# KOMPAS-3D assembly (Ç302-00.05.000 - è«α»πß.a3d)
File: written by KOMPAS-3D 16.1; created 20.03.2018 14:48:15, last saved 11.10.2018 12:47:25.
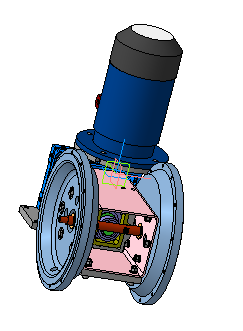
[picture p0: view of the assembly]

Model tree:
1. Массив по концентрической сетке:1  (2 pattern instances)
     Шаг 2 = 360
2. Массив по концентрической сетке:2  (4 pattern instances)
     Шаг 2 = 360
3. Сечение поверхностью:3
4. Сечение поверхностью:4
5. Сечение поверхностью:2  (labels: А302-00.05.000; C:\Program Files\ASCON\KOMPAS-3D V16\Sys\bo_atr.lat; SYSTEM_PROPERTY_ADDITIONAL_FOR:5.000000)
     Расстояние = -4; Расстояние = 4; Расстояние = 1

Referenced files in Z:\Мембранные насосы\Мембранный электропривод\А302-00.00.000 - ASTRA-302 (МЭ200)\3Д\: А302-00.20.000 - Мотор-редуктор.a3d, А302-00.05.002 - Ловитель.m3d, А302-00.05.001 - Основание.m3d
Referenced files in C:\Program Files\ASCON\KOMPAS-3D V16\Libs\PartLib\DATA\vault\Methods\Kompas\3D\: PLib_Washer_1_712.m3d
Referenced files in C:\Program Files\ASCON\KOMPAS-3D V16\Libs\PartLib\DATA\VAULT\Methods\kompas\3d\: PLib_Washer_2_712.m3d, PLib_Bolt_1_900.m3d, PLib_Nut_OST92_900.m3d
Referenced files in Z:\1 ПКИ 3D\1 Крепеж стандартный\Подшипник\: Подшипник радиально-упорный 80х40х18 7208 BEP SKF.m3d, Подшипниковый узел UCF207 ISB EcoLine.m3d
Referenced files in Z:\Мембранные насосы\Мембранный электропривод\А302-00.00.000 - ASTRA-302 (МЭ200)\3Д ПВХ\Отработка\: Фиксатор.m3d, Упор.m3d, Упор-1.m3d
Referenced files in Z:\Мембранные насосы\Мембранный электропривод\А302-00.00.000 - ASTRA-302 (МЭ200)\Чертежи\: А302-00.20.000  - Мотор-редуктор.spw
Referenced files: GRAPHIC.TDP
Referenced files in \\192.168.87.28\Konstructor_doc\Мембранные насосы\Мембранный электропривод\А302-00.00.000 - ASTRA-302 (МЭ200)\Чертежи\: А302-00.05.002 - Ловитель.cdw, А302-00.05.001 - Основание.cdw
Referenced files in Z:\Мембранные насосы\Мембранный электропривод\А302-00.00.000 - ASTRA-302 (МЭ200)\3Д ПВХ\: А302-01.05.012 - Фиксатор.cdw, А302-01.05.014 - Упор.cdw
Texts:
  Сталь 12Х18Н10Т ГОСТ 5632-72
  Шайба C.8.21 ГОСТ 11371-78
  Крепежное изделие ГОСТ
  Сталь 20 ГОСТ 1050-2013
  Шайба C 8.04.019 ГОСТ 6958-78
  Сталь 30Х13 ГОСТ 5632-72
  Шайба 8 30Х13 019 ГОСТ 6402-70
  Болт М8-6gx30.58.019 ГОСТ 7805-70
  hole1
  hole2
  Гайка М8-6H.5.019 ГОСТ 5915-70
  bcut1
  hcut1
  cut1
  Подшипник радиально-упорный 80х40х18 7208 BEP SKF
  Подшипниковый узел UCF207 ISB EcoLine
  (-) Подшипниковый узел UCF207 ISB EcoLine
  ГОСТ 11371-78
  ГОСТ 6958-78
  ГОСТ 6402-70
  ГОСТ 7805-70
  М8-6gx30.58.019
  ГОСТ 5915-70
